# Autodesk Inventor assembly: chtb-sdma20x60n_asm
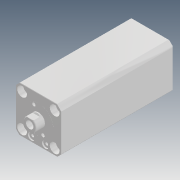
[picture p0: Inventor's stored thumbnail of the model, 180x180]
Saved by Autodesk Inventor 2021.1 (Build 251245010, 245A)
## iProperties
Created: 2018-05
Part Number: chtb-sdma20x60n_asm
Description: STEP AP214
Document SubType Name: Assembly
Designer: user
Title: chtb-sdma20x60n_asm.STEP
Revision Number: ÈÎºÎ
Sending System: SolidWorks 2016
Preprocessor: SwSTEP 2.0
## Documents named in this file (5)
- D:\Vault_2016\Projekty\Clamptek\Hydraulic\CHTB\CHTB-20\Inventor\CHTB-SDMA20x60N\chtb-sdma20x60n_asm.iam
- D:\Vault_2016\Projekty\Clamptek\Hydraulic\CHTB\CHTB-20\Inventor\CHTB-SDMA20x60N\CHTB-SDMA20X60NBT.ipt
- D:\Vault_2016\Projekty\Clamptek\Hydraulic\CHTB\CHTB-20\Inventor\CHTB-SDMA20x60N\CHTB-SDMA20X60NHSG.ipt
- D:\Vault_2016\Projekty\Clamptek\Hydraulic\CHTB\CHTB-20\Inventor\CHTB-SDMA20x60N\QG_3.ipt
- D:\Vault_2016\Projekty\Clamptek\Hydraulic\CHTB\CHTB-20\Inventor\CHTB-SDMA20x60N\socket set screw flat point_iso_ISO 4026 - M5 x 5-N.ipt
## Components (5 placed, 5 different names)
1. CHTB-SDMA20X60NBT_1
2. CHTB-SDMA20X60NHSG_2
3. QG_3_3
4. socket set screw flat point_iso_ISO 4026 - M5 x 5-N_4
5. socket set screw flat point_iso_ISO 4026 - M5 x 5-N_5
